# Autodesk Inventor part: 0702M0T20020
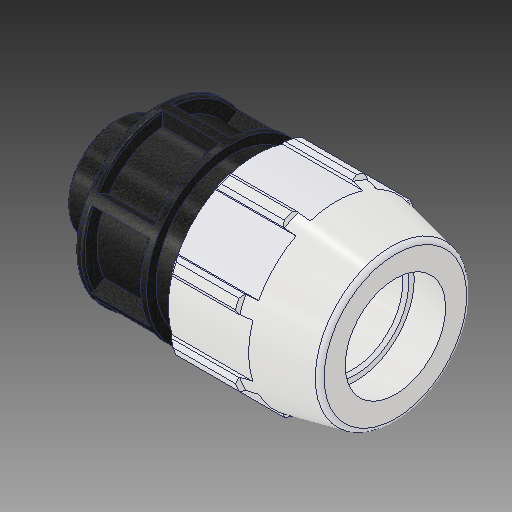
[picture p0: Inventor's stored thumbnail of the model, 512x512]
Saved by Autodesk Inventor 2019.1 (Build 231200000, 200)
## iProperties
Created: 2017-02
Part Number: 0702M0T20020
Material: PVC-Piping
Description: PLASSON MALE ADAPTOR 2'' - 2''M
Document SubType Name: Modeling
Designer: KIM
Mass: 92.6774 g
Surface Area: 199.44 cm^2
Volume: 66.1981 cm^3
Density: 1.4 g/cm^3
Appearance: PTFE
Author: KIM
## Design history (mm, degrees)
derived "0702M0T.ipt"
feature "Solid1::0702M0T.ipt"
tag "TaggingFeature1"
body "Solid1"
other parameters: "d2" = 60.1, "d4" = 23.83971, "d5" = 41.7195, "d7" = 113.03, "d8" = 84.7725, "d9" = 23.83971, "d11" = 4.76794, "d12" = 90.424, "d13" = 120 deg, "d14" = 90.15, "d15" = 12 deg, "d16" = 101.727, "d18" = 3.005, "d19" = 35 deg, "d20" = 17.5 deg, "d21" = 105.1179, "d23" = 0, "d25" = 360 deg, "d27" = 2.2606, "d34" = 5.6515, "d36" = 0, "d42" = 41.7195, "d43" = 3.3909, "d46" = 1.803, "d51" = 166.878, "d52" = 25.908, "d53" = 1.202, "d55" = 360 deg, "d57" = 59.614, "d58" = 41.7298, "d59" = 33.3756, "d61" = 30.988, "d_" = 60.1, "E_" = 113.03, "H_" = 166.878, "l_" = 134.112, "l_2" = 25.908, "G_" = 59.614
